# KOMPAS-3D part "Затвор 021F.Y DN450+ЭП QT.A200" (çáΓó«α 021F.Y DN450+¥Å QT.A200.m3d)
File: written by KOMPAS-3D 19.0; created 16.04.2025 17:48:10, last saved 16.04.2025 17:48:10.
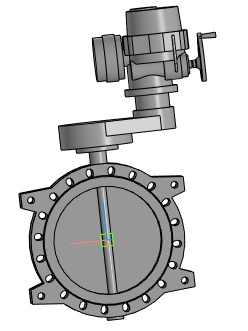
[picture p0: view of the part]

Document properties: Полное имя файла: Затвор 021F.Y DN450+ЭП QT.A200.a3d

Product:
- Part/product: Затвор 021F.Y DN450+ЭП QT.A200
    Масса: 378.859

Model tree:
1. Операция без истории:1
